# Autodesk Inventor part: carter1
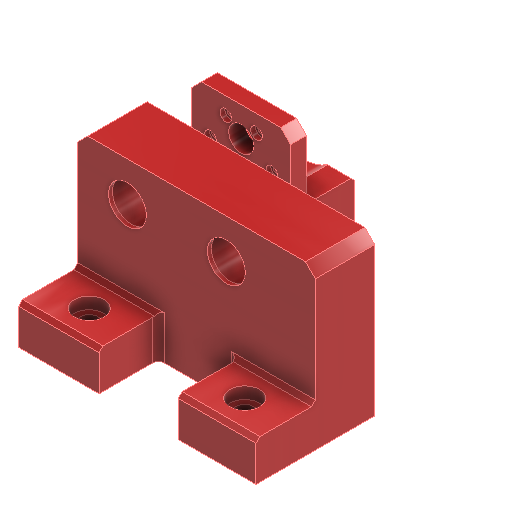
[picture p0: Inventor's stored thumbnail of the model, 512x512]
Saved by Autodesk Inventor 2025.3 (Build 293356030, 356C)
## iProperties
Created: 2026-09
Part Number: carter1
Material: Plastica PET
Document SubType Name: Modeling
Designer: R5800u
Density: 1.541 g/cm^3
Appearance: Rosso
Author: R5800u
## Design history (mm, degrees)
sketch "Schizzo1"
  geometry: L1 (-75, 20)-(45, 20); L2 (45, 20)-(45, -40); L3 (45, -40)-(-75, -40); L4 (-75, -40)-(-75, 20); C1 r 11 at (0, 0); C2 r 11 at (-50, 0); 1 further point
  constraints: 8 end point, 2 centre point, 2 parallel, 1 coincident, 1 horizontal, 1 perpendicular
  dimensions: "d0" = 22 diameter of C1; "d1" = 22 diameter of C2; "d2" = 50 distance of point (0, 0) C2.centre; "d3" = 40 distance from line of point (0, 0) L3; "d5" = 120 distance of L2.end L3.end; "d8" = 60 distance of L3.end L1.start; "d79" = 25 distance from line of L4 C2.centre; "d80" = 40 distance from line of L3 C2.centre
extrude "Estrusione1" new body sketch "Schizzo1" distance "d6" = 30; taper "d7" = 0 deg
sketch "Schizzo2"
  geometry: L1 (0, 0)-(120, 0) reference; L2 (0, 0)-(120, 0); L3 (120, 0)-(120, 60); L4 (120, 60)-(0, 60); L5 (0, 60)-(0, 0); 2 further points
  constraints: 8 end point, 2 parallel, 1 horizontal, 1 perpendicular
  dimensions: "d9" = 60 distance of L3.end L2.end
extrude "Estrusione2" join sketch "Schizzo2" distance "d10" = 20; taper "d11" = 0 deg
chamfer "Smusso2" distance "d15" = 2; stored, may be unused: second distance "d16" = 2, angle "d17" = 45 deg
sketch "Schizzo3"
  geometry: L1 (120, -30)-(0, -30) reference; L2 (99.309, -30)-(99.309, -60); L3 (120, -60)-(0, -60) reference; 2 further points
  constraints: 2 end point, 2 point on line, 1 midpoint, 1 vertical
hole "Foro1" sketch "Schizzo3" at (99.309, -45) diameter "d18" = 9; stored, may be unused: countersink angle "d22" = 90 deg, drill point angle "d24" = 118 deg; dims "d19" = 6, "d20" = 15, "d21" = 6, "d23" = 8
node "Piano di lavoro1"
mirror "Speculare1"
sketch "Schizzo4"
  geometry: C1 r 11 at (-50, 0) reference; C2 r 11 at (0, 0) reference; C3 r 9.5 at (-50, 0); C4 r 9.5 at (0, 0); 1 further point
  constraints: 2 centre point
  dimensions: "d25" = 1.5 radial gap between concentric circles of C1 C3; "d26" = 1.5 radial gap between concentric circles of C2 C4
extrude "Estrusione3" join sketch "Schizzo4" distance "d27" = 2; taper "d28" = 0 deg
sketch "Schizzo5"
  geometry: L1 (0, 0)-(75, 0); L2 (75, 20)-(75, -60) reference; L3 (25, 0)-(25, -60); L4 (75, -60)-(-45, -60) reference; L5 (25, -20)-(75, -20); C1 r 18.5 at (50, -7) reference; C2 r 9.5 at (0, 0) reference; 4 further points
  constraints: 6 end point, 4 point on line, 1 horizontal, 1 midpoint, 1 perpendicular
  dimensions: "d29" = 50 distance between parallel lines of L2 L3
extrude "Estrusione4" join sketch "Schizzo5" distance "d30" = 60; taper "d31" = 0 deg
node "Piano di lavoro2"
sketch "Schizzo6"
  geometry: L1 (-25, -53)-(-25, -13) reference; L2 (-25, -13)-(25, -13); L3 (25, -13)-(25, 22); L4 (25, 22)-(-25, 22); L5 (-25, 22)-(-25, -13); C1 r 18.5 at (0, 0) reference; C2 r 1.6 at (-7.75, 13.423) reference; C3 r 1.6 at (7.75, 13.423) reference; C4 r 1.6 at (-15.5, 0) reference; C5 r 1.6 at (15.5, 0) reference; C6 r 6.25 at (0, 7) reference; 3 further points
  constraints: 8 end point, 2 parallel, 1 horizontal, 1 perpendicular
  dimensions: "d34" = 35 distance of L3.end L2.end
extrude "Estrusione5" join sketch "Schizzo6" distance "d32" = 8; taper "d33" = 0 deg
chamfer "Smusso3" distance "d35" = 10; stored, may be unused: second distance "d36" = 2, angle "d37" = 45 deg
chamfer "Smusso4" distance "d38" = 5; stored, may be unused: second distance "d39" = 2, angle "d40" = 45 deg
sketch "Schizzo7"
  geometry: C1 r 1.6 at (-7.75, 13.423) reference; C2 r 1.6 at (7.75, 13.423) reference; C3 r 1.6 at (-15.5, 0) reference; C4 r 1.6 at (15.5, 0) reference; 5 further points
  constraints: 4 coincident
hole "Foro2" sketch "Schizzo7" at (-7.75, 13.423), (7.75, 13.423), (-15.5, 0), (15.5, 0) diameter "d41" = 3.4; stored, may be unused: countersink angle "d45" = 90 deg, drill point angle "d47" = 118 deg; dims "d42" = 6, "d43" = 5.8, "d44" = 2.4, "d46" = 8
sketch "Schizzo8"
  geometry: L1 (50, 0)-(120, 0) reference; L2 (120, 0)-(120, 60) reference; L3 (120, 60)-(0, 60) reference; L4 (0, 60)-(0, -60) reference; L5 (50, -60)-(0, -60) reference; L6 (50, 0)-(50, -60) reference; L7 (0, 0)-(50, 0); L8 (0, -5)-(50, -5); L9 (5, -55)-(5, 55); L10 (5, 55)-(115, 55); L11 (115, 55)-(115, 5); L12 (115, 5)-(45, 5); L13 (45, 5)-(45, -55); L14 (45, -55)-(5, -55); C1 r 4.5 at (20.691, 45) reference; C2 r 4.5 at (99.309, 45) reference; 3 further points
  constraints: 16 end point, 1 horizontal, 1 midpoint, 1 parallel, 5 other
  dimensions: "d48" = 5 distance between parallel lines of L7 L8; "d49" = 5 distance between parallel lines of L4 L9
extrude "Estrusione6" cut sketch "Schizzo8" distance "d50" = 30; taper "d51" = 0 deg
fillet "Raccordo1" dims "d52" = 20
chamfer "Smusso5" distance "d53" = 2; stored, may be unused: second distance "d54" = 2, angle "d55" = 45 deg
node "Piano di lavoro4"
sketch "Schizzo9"
  geometry: C1 r 12 at (0, 0); C2 r 11 at (0, 0) reference; 1 further point
  constraints: 1 centre point, 1 coincident
  dimensions: "d58" = 24 diameter of C1
extrude "Estrusione7" cut sketch "Schizzo9" distance "d59" = 1; taper "d60" = 0 deg
sketch "Schizzo10"
  geometry: C1 r 11 at (50, 0) reference; C2 r 11 at (50, 0) reference; C3 r 11.5 at (50, 0); 1 further point
  constraints: 1 centre point
  dimensions: "d61" = 0.5 radial gap between concentric circles of C1 C3
extrude "Estrusione8" cut sketch "Schizzo10" distance "d62" = 1; taper "d63" = 0 deg
chamfer "Smusso6" distance "d64" = 5; stored, may be unused: second distance "d65" = 2, angle "d66" = 45 deg
sketch "Schizzo11"
  geometry: 1 further point
sketch "Schizzo12"
  geometry: L1 (114, 6)-(6, 6); L2 (6, 6)-(6, 24); L3 (6, 24)-(114, 24); L4 (114, 24)-(114, 6); L5 (55, 0)-(120, 0) reference; L6 (120, 0)-(120, 60) reference; L7 (0, 60)-(0, -60) reference; 1 further point
  constraints: 8 end point, 2 parallel, 1 horizontal, 1 perpendicular
  dimensions: "d67" = 6 distance between parallel lines of L5 L1; "d68" = 18 distance of L3.end L1.start; "d69" = 6 distance between parallel lines of L6 L4; "d70" = 6 distance between parallel lines of L7 L2
extrude "Estrusione9" cut sketch "Schizzo12" distance "d71" = 40; taper "d72" = 0 deg
fillet "Raccordo2" dims "d73" = 9
sketch "Schizzo13"
  geometry: L1 (120, -60)-(0, -60) reference; L2 (120, -30)-(0, -30) reference; L3 (40.691, -60)-(80.691, -60); L4 (80.691, -60)-(80.691, -30); L5 (80.691, -30)-(40.691, -30); L6 (40.691, -30)-(40.691, -60); C1 r 4.5 at (20.691, -45) reference; 3 further points
  constraints: 8 end point, 2 parallel, 2 point on line, 1 horizontal, 1 perpendicular
  dimensions: "d74" = 40 distance between parallel lines of L4 L6; "d75" = 20 distance from line of C1.centre L6
extrude "Estrusione10" cut sketch "Schizzo13" stored distance "d76" = 120; taper "d77" = 0 deg
fillet "Raccordo3" dims "d78" = 3
node "Solido1"
node "Riferimento1"
node "Riferimento2"
node "Riferimento3"
node "Riferimento4"
node "Riferimento5"
node "Riferimento6"
node "Riferimento7"
node "Linea chiusa proiettata1"
node "Linea chiusa proiettata2"
other parameters: "d57" = -1
